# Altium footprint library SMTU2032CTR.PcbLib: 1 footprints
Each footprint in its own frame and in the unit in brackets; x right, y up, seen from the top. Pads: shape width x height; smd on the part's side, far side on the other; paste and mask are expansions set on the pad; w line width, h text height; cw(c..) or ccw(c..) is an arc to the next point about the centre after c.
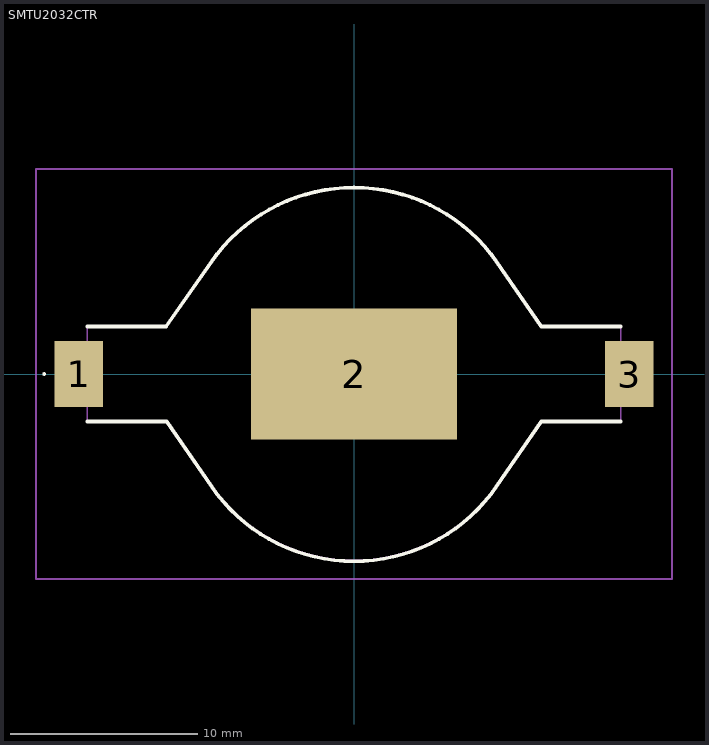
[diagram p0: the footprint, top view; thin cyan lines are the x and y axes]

## SMTU2032CTR [mm]
pads (3):
  rect 2.6x3.5 smd: 1(-14.7,0) 3(14.7,0)
  rect 11x7 smd: 2(0,0)
Top Overlay:
  lines w0.1: -16.6,0 -16.6,0 ; -16.6,0 ccw(c-16.55,0) -16.5,0 ; -16.6,0 cw(c-16.55,0) -16.5,0 ; -16.5,0 -16.5,0
  lines w0.2: -14.25,-2.54 -10,-2.54 -7.62,-6 ; -14.25,2.54 -10.05,2.54 -7.62,6 ; -7.622,-5.997 ccw(c0,-0.758) 7.622,-5.997 ; -7.619,6.003 cw(c0,0.649) 7.619,6.003 ; 7.62,6 10,2.54 14.25,2.54 ; 14.25,-2.54 10,-2.54 7.62,-6 ; -7.62,6 -7.62,6 ; 7.62,-6 7.62,-6
Mechanical 15:
  lines w0.1: -7.62,-6 -10.05,-2.54 -14.25,-2.54 -14.25,2.54 -10.05,2.54 -7.62,6 ; -7.619,-6.003 ccw(c0,-0.649) 7.619,-6.003 ; -7.619,6.003 cw(c0,0.649) 7.619,6.003 ; 7.62,6 10.05,2.54 14.25,2.54 14.25,-2.54 10.05,-2.54 7.62,-6 ; -7.62,6 -7.62,6 ; 7.62,-6 7.62,-6
Mechanical 20:
  lines w0.1: -17,-10.96 17,-10.96 17,10.96 -17,10.96 -17,-10.96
